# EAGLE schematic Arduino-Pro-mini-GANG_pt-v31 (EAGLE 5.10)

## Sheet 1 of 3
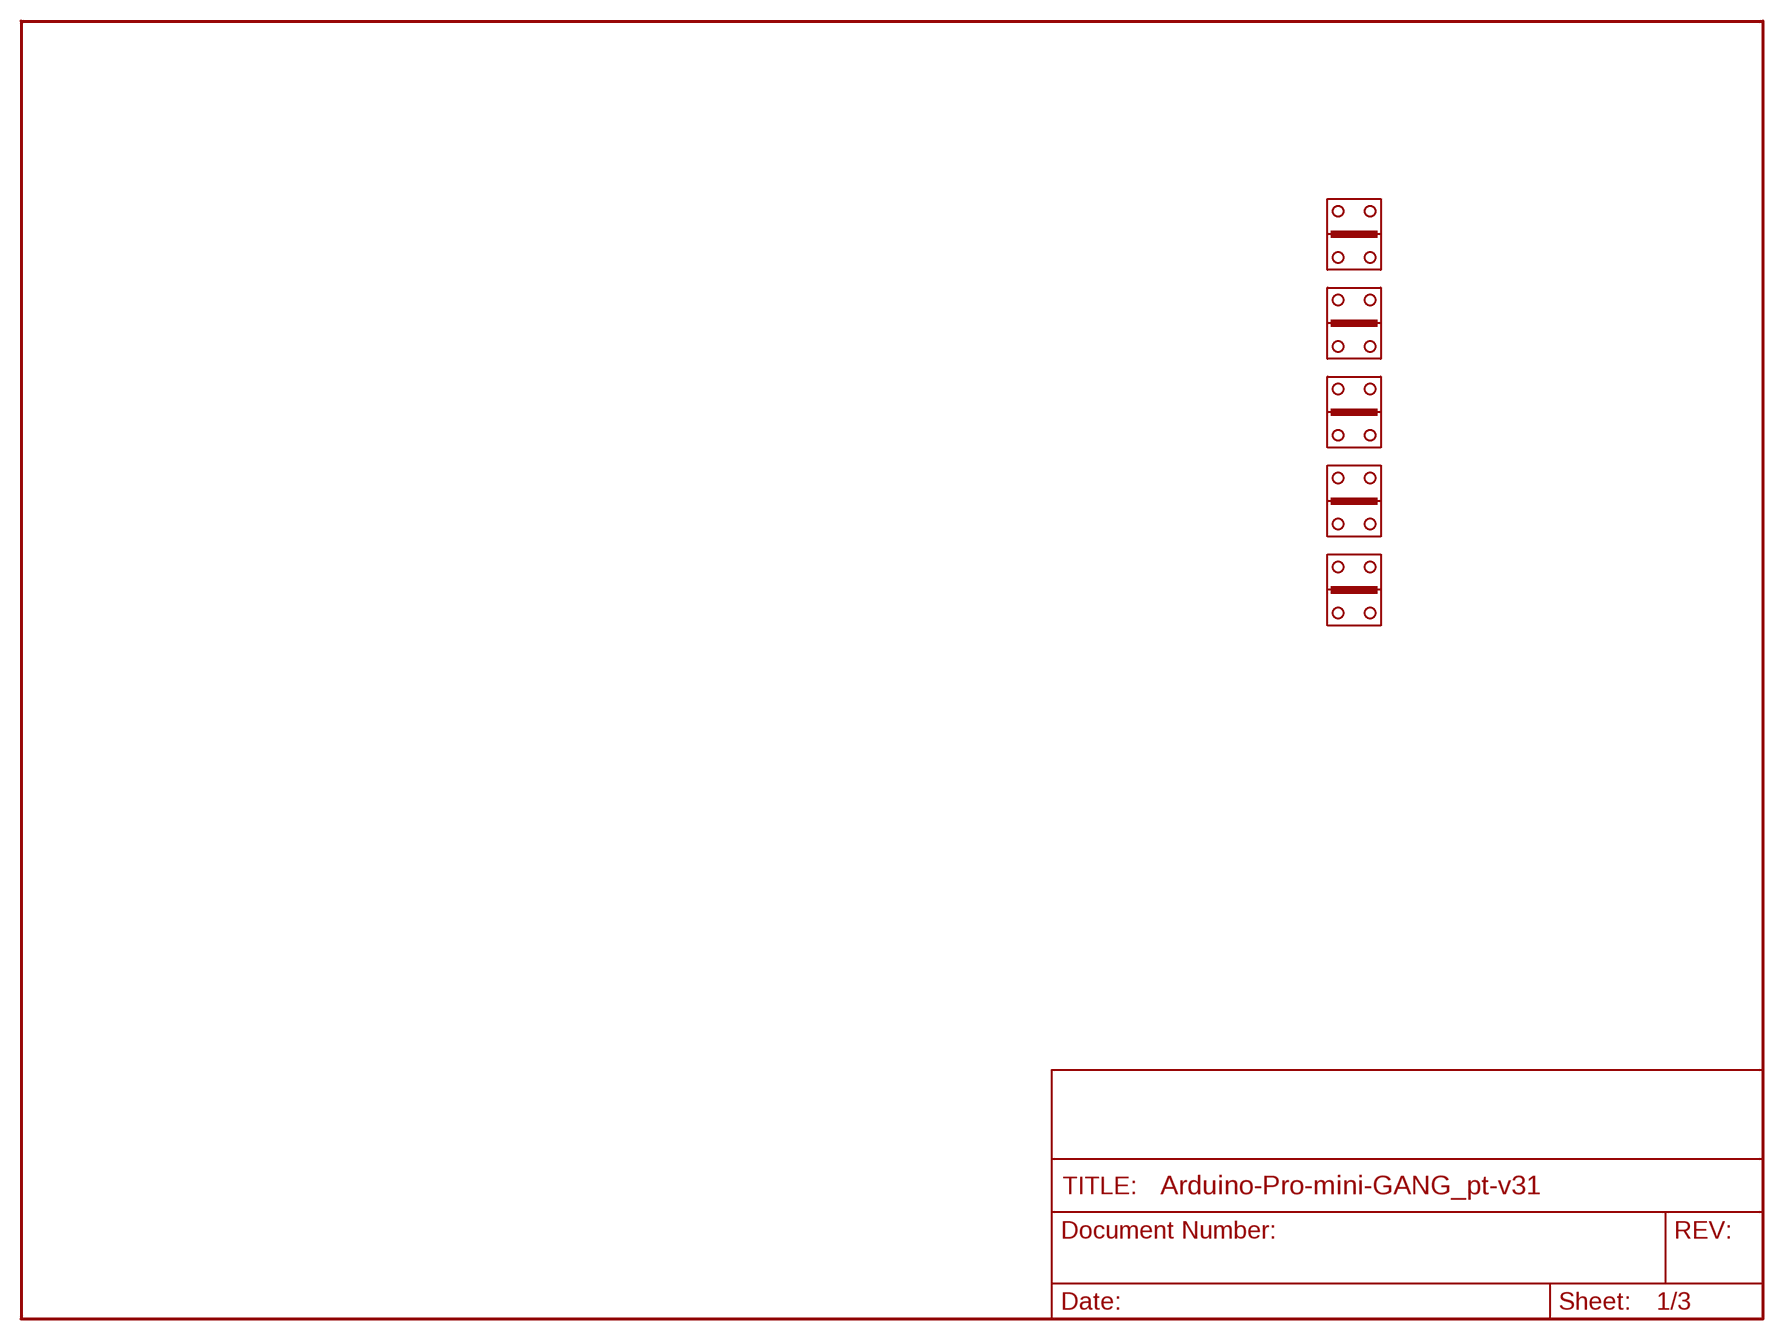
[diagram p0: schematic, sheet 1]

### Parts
U$4  GOLD_HINDGESTANDARD  [GOLD_HINDGE]
U$5  GOLD_HINDGESTANDARD  [GOLD_HINDGE]
U$6  GOLD_HINDGESTANDARD  [GOLD_HINDGE]
U$7  GOLD_HINDGESTANDARD  [GOLD_HINDGE]
U$8  GOLD_HINDGESTANDARD  [GOLD_HINDGE]

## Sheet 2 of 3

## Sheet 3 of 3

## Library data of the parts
U$4-U$8 = Testing:GOLD_HINDGE

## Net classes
0 Default: width 0.203 mm
1 VCC: width 0.305 mm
